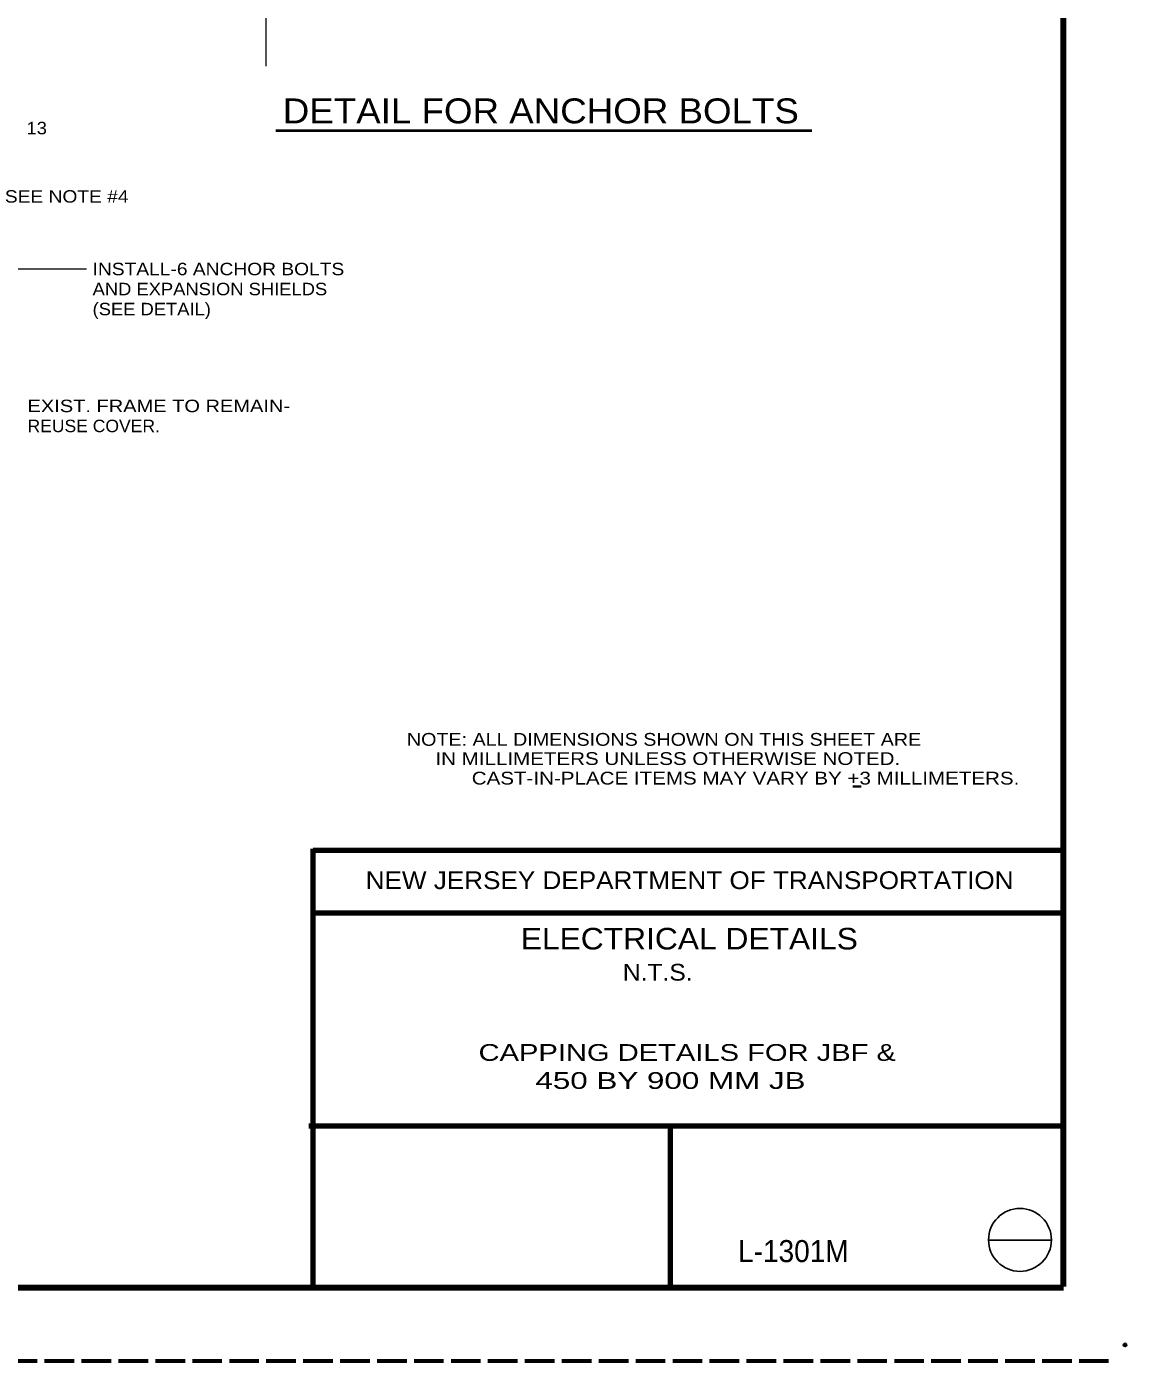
# Model space of a CAD drawing. Extents: x 312583 to 312853, y 144419 to 144586.
# Drawn here: x 312785.9 to 312852.8, y 144418.6 to 144499.9 of the extents above; entities that cross this region are included whole.
import ezdxf
from ezdxf.enums import TextEntityAlignment as Align

# ---------------------------------------------------------------- set-up
doc = ezdxf.new("R2010")
doc.units = 0
doc.header["$LTSCALE"] = 0.3
doc.header["$PDMODE"] = 32
doc.header["$PDSIZE"] = 0.15
doc.linetypes.add('LONG_DASHED', pattern=[7.5, 6, -1.5])
doc.layers.add('1', color=7, linetype='Continuous', lineweight=40)
doc.layers.add('2', color=7, linetype='Continuous', lineweight=13)

msp = doc.modelspace()

# ---------------------------------------------------------------- linework, layer by layer
at = {"layer": '1', "lineweight": 158}
for p, q in [((312849, 144423.1446), (312849, 144585.0846)), ((312616.5, 144423.0846), (312849, 144423.0846))]:
    msp.add_line(p, q, dxfattribs=at)
at = {"layer": '1', "lineweight": 35}
msp.add_line((312836.1686, 144453.6102), (312836.6785, 144453.6102), dxfattribs=at)
at = {"layer": '1', "lineweight": 80}
for p, q in [((312803.31, 144423.1446), (312803.31, 144449.8146)), ((312803.31, 144449.7246), (312849, 144449.7246)), ((312803.31, 144445.9146), (312849, 144445.9146)), ((312803.0384, 144432.9349), (312849, 144432.9349)), ((312825.0494, 144432.9349), (312825.0494, 144423.1446))]:
    msp.add_line(p, q, dxfattribs=at)
at = {"layer": '1', "lineweight": 25}
msp.add_line((312844.4384, 144425.966), (312848.2794, 144425.966), dxfattribs=at)
at = {"layer": '1', "linetype": 'LONG_DASHED', "lineweight": 60}
msp.add_line((312851.75, 144418.5846), (312583.526, 144418.5846), dxfattribs=at)
msp.add_line((312851.75, 144418.5846), (312583.526, 144418.5846), dxfattribs=at)
at = {"layer": '1', "lineweight": 25}
msp.add_circle((312846.3494, 144425.9805), 1.9159, dxfattribs=at)
at = {"layer": '1'}
msp.add_point((312852.75, 144419.5846), dxfattribs=at)
at = {"layer": '2'}
for p, q in [((312800.4429, 144497.4998), (312800.4429, 144509.0764)), ((312780.7387, 144485.1377), (312789.494, 144485.1377))]:
    msp.add_line(p, q, dxfattribs=at)
at = {"layer": '2', "lineweight": 40}
msp.add_line((312801.0305, 144493.5744), (312833.6797, 144493.5744), dxfattribs=at)

# ---------------------------------------------------------------- texts
at = {"layer": '1'}
for s, width, p in [('NOTE: ALL DIMENSIONS SHOWN ON THIS SHEET ARE', 1.15, (312809.0107, 144456.0854)), ('     IN MILLIMETERS UNLESS OTHERWISE NOTED.', 1.2, (312809.0106, 144454.9154)), ('CAST-IN-PLACE ITEMS MAY VARY BY +3 MILLIMETERS.', 1.2, (312812.9615, 144453.7245))]:
    msp.add_text(s, height=0.78, dxfattribs=dict(at, width=width)).set_placement(p)
for s, height, width, p in [('NEW JERSEY DEPARTMENT OF TRANSPORTATION', 1.08, 1.1, (312826.2285, 144447.3546)), ('ELECTRICAL DETAILS', 1.315, 1.1, (312826.2109, 144443.6759)), ('L-1301M', 1.342, 0.95, (312832.5479, 144424.6277))]:
    msp.add_text(s, height=height, dxfattribs=dict(at, width=width)).set_placement(p, align=Align.CENTER)
at = {"layer": '2'}
for s, height, width, p in [('DETAIL FOR ANCHOR BOLTS', 1.52, 1.1, (312817.1691, 144494.0075)), ('    N.T.S.  ', 1.02, 1.1, (312823.87, 144441.778)), ('   CAPPING DETAILS FOR JBF & ', 1.02, 1.3, (312825.5936, 144436.8909)), ('450 BY 900 MM JB  ', 1.02, 1.4, (312825.5936, 144435.1812))]:
    msp.add_text(s, height=height, dxfattribs=dict(at, width=width)).set_placement(p, align=Align.CENTER)
for s, width, p in [('13 ', 1.1, (312785.8447, 144493.3417)), ('SEE NOTE #4', 1.15, (312784.526, 144489.1765)), ('INSTALL-6 ANCHOR BOLTS', 1.15, (312789.8697, 144484.7534)), ('AND EXPANSION SHIELDS', 1.1, (312789.8697, 144483.5334)), ('(SEE DETAIL)', 1.1, (312789.8697, 144482.3134)), ('EXIST. FRAME TO REMAIN-', 1.2, (312785.906, 144476.4121)), ('REUSE COVER.', 1.05, (312785.906, 144475.1921))]:
    msp.add_text(s, height=0.76, dxfattribs=dict(at, width=width)).set_placement(p)

doc.saveas('drawing.dxf')
